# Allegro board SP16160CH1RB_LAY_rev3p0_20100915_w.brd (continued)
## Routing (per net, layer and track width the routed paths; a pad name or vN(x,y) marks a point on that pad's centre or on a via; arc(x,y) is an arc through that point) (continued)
ADC_CLK_N: length 20.5
  TOP w0.203: C173.1 98.73,90.91 98.73,97.69 95.5,100.91 95.5,105.33 C177.1 R162.1 95.5,107.01 95.5,109.17 95.58,109.24 U1.26
ADC_CLK_P: length 20.5
  TOP w0.203: C172.1 98.37,90.91 98.37,97.54 95.15,100.76 95.15,105.33 C174.1 R162.2 95.15,107.01 95.15,109.18 95.08,109.24 U1.25
ADC_VIN_IN: length 11.4
  TOP w0.203: 90.4,123.04 C73.2 90.07,122.7 v1(90.07,122.7) ; 90.4,123.04 90.4,123.04 90.78,123.04 92.15,121.67 92.15,121.08 91.69,120.62 L3.1 ; 90.4,123.04 90.4,123.42 89.39,124.43 88.85,124.43 88.08,123.66 88.08,123.23 L7.2 ; L3.1 91.69,120.52 92.15,120.07 92.15,119.2 92.08,119.13 92.08,118.83 U1.67 ; L3.1 v1(91.44,120.57)
  BOTTOM w0.203: C75.2 v1(90.07,122.7) ; R44.2 v1(91.44,120.57)
ADC_VIN_IP: length 12.3
  TOP w0.203: 92.96,120.57 92.96,120.52 92.51,120.07 92.51,119.2 92.58,119.13 92.58,118.83 U1.66 ; 92.96,120.57 92.96,120.62 92.51,121.08 92.51,121.82 91.03,123.29 91.03,123.67 91.04,123.67 ; 92.96,120.57 v1(93.22,120.57) ; 91.04,123.67 C73.1 91.37,124 v1(91.37,124) ; 91.04,123.67 90.65,123.67 89.53,124.79 88.71,124.79 87.83,123.91 87.4,123.91 L10.2
  BOTTOM w0.203: C74.1 v1(91.37,124) ; R43.1 v1(93.22,120.57)
ADC_VIN_QN: length 11
  TOP w0.203: 90.45,105.24 C83.2 90.3,105.38 v1(90.12,105.57) ; 90.45,105.24 90.45,105.23 90.81,105.23 92.15,106.58 92.15,107.16 91.69,107.62 L6.1 91.69,107.72 92.15,108.18 92.15,109.04 92.08,109.12 92.08,109.42 U1.19 ; 90.45,105.24 90.45,104.87 89.48,103.9 88.94,103.9 88.17,104.68 88.17,105.11 L8.2
  BOTTOM w0.203: v1(90.12,105.57) 90.43,105.25 C85.2 ; R49.2 v1(91.44,107.67)
ADC_VIN_QP: length 11.9
  TOP w0.203: 91.06,104.62 91.06,104.63 91.06,104.98 92.51,106.43 92.51,107.16 92.96,107.62 92.96,107.72 92.51,108.18 92.51,109.04 92.58,109.12 92.58,109.42 U1.20 ; 91.06,104.62 C83.1 91.21,104.48 v1(91.39,104.29) ; 91.06,104.62 90.7,104.62 89.62,103.54 88.8,103.54 87.92,104.42 87.49,104.42 87.38,104.32
  BOTTOM w0.203: 91.08,104.71 91.08,104.6 v1(91.39,104.29) ; R48.1 v1(93.22,107.67)
ADC_VRM_I: length 17.7
  TOP w0.203: C41.2 89.92,117.62 U1.2
  TOP w0.381: v1(89.61,120.93) C42.2 C41.2
  BOTTOM w0.508: R45.2 95,124.74 C43.1
  BOTTOM w0.635: C43.1 93.6,125.73 89.92,125.73 88.34,124.16 88.34,121.79 89.2,120.93 v1(89.61,120.93)
ADC_VRM_Q: length 17.3
  TOP w0.203: C44.2 89.71,109.93 89.71,110.06 90.28,110.62 U1.16
  TOP w0.381: C44.2 C45.2 v1(89.61,107.72)
  BOTTOM w0.508: C46.1 94.97,103.5 R50.2
  BOTTOM w0.635: C46.1 93.6,102.51 89.92,102.51 88.34,104.09 88.34,106.45 v1(89.61,107.72)
D0/1+I: length 35
  TOP w0.203: U1.60 95.5,118.9 95.5,127.41 98.88,130.78 119.34,130.78 H4.B5
D0/1+Q: length 29.3
  TOP w0.203: H4.B21 119.32,98.81 111.38,98.81 106.2,103.99 100.41,103.99 96.74,107.66 96.74,108.98 96.58,109.13 U1.28
D0/1-I: length 37.7
  TOP w0.203: H4.A5 120.98,131.14 98.73,131.14 95.15,127.56 95.15,118.89 U1.61
D0/1-Q: length 30.8
  TOP w0.203: U1.29 97.09,109.41 97.09,107.81 100.55,104.34 106.34,104.34 111.53,99.16 120.96,99.16 H4.A21
D2/3+I: length 32.4
  TOP w0.203: H4.B6 119.32,128.8 99.34,128.8 96.47,125.93 96.47,118.93 U1.58
D2/3+Q: length 27.1
  TOP w0.203: U1.30 97.61,109.39 97.61,108.28 99.7,106.2 106.96,106.2 112.37,100.79 119.33,100.79 H4.B20
D2/3-I: length 35.1
  TOP w0.203: H4.A6 120.96,129.16 99.19,129.16 96.11,126.08 96.11,118.86 U1.59
D2/3-Q: length 28.6
  TOP w0.203: H4.A20 120.98,101.14 112.52,101.14 107.11,106.55 99.84,106.55 98.08,108.31 U1.31
D4/5+I: length 30
  TOP w0.203: H4.B7 120.15,125.98 119.33,126.8 99.09,126.8 97.56,125.27 97.56,118.84 U1.56
D4/5+Q: length 25.1
  TOP w0.203: H4.B19 119.33,102.79 112.42,102.79 107.39,107.82 99.47,107.82 98.6,108.69 98.6,109.44 U1.32
D4/5-I: length 32.8
  TOP w0.203: H4.A7 120.97,127.15 98.94,127.15 97.21,125.42 97.21,118.95 U1.57
D4/5-Q: length 26.6
  TOP w0.203: U1.33 99.08,108.71 99.61,108.18 107.54,108.18 112.57,103.15 120.97,103.15 H4.A19
D6/7+I: length 26.2
  TOP w0.203: U1.54 98.58,121.85 101.52,124.79 119.33,124.79 H4.B8
D6/7+Q: length 23.1
  TOP w0.203: H4.B18 119.32,104.8 112.88,104.8 108.31,109.37 101.42,109.37 101.04,109.75 99.91,109.75 U1.34
D6/7-I: length 28.9
  TOP w0.203: U1.55 98.08,121.85 101.38,125.15 120.98,125.15 H4.A8
D6/7-Q: length 24.4
  TOP w0.203: H4.A18 120.97,105.16 113.02,105.16 108.45,109.73 101.57,109.73 101.18,110.12 U1.35
D8/9+I: length 23.8
  TOP w0.203: U1.52 99.49,118.91 99.49,120.8 101.47,122.78 119.34,122.78 H4.B9
D8/9+Q: length 21.8
  TOP w0.203: H4.B17 119.31,106.81 113.28,106.81 109.55,110.54 100.84,110.54 100.76,110.62 U1.36
D8/9-I: length 26.6
  TOP w0.203: H4.A9 120.98,123.14 101.33,123.14 99.14,120.95 99.14,118.88 U1.53
D8/9-Q: length 24
  TOP w0.203: H4.A17 120.96,107.16 113.43,107.16 109.7,110.9 101.09,110.9 100.87,111.12 U1.37
D10/11+I: length 21.5
  TOP w0.203: H4.B10 119.32,120.8 104.57,120.8 101.39,117.62 U1.50
D10/11+Q: length 21.4
  TOP w0.203: H4.B16 119.33,108.79 113.11,108.79 110.27,111.62 U1.38
D10/11-I: length 23.6
  TOP w0.203: H4.A10 120.96,121.16 104.42,121.16 101.39,118.12 U1.51
D10/11-Q: length 23.6
  TOP w0.203: U1.39 100.57,112.12 100.71,111.98 110.42,111.98 113.25,109.14 120.98,109.14 H4.A16
D12/13+I: length 21.1
  TOP w0.203: H4.B11 119.33,118.8 104.24,118.8 102.34,116.89 100.84,116.89 100.57,116.62 U1.48
D12/13+Q: length 21
  TOP w0.203: H4.B15 119.33,110.79 113,110.79 111.18,112.62 U1.40
D12/13-I: length 23.2
  TOP w0.203: U1.49 100.51,117.12 100.63,117.25 102.19,117.25 104.09,119.15 120.97,119.15 H4.A11
D12/13-Q: length 23.2
  TOP w0.203: U1.41 100.57,113.12 100.71,112.98 111.32,112.98 113.15,111.15 120.97,111.15 H4.A15
D14/15+I: length 20.7
  TOP w0.203: U1.46 100.56,115.62 100.74,115.8 103.12,115.8 104.11,116.79 119.33,116.79 H4.B12
D14/15+Q: length 20.6
  TOP w0.203: U1.42 113,113.62 113.82,112.8 119.32,112.8 H4.B14
D14/15-I: length 22.8
  TOP w0.203: H4.A12 120.98,117.14 103.97,117.14 102.98,116.15 100.31,116.15 U1.47
D14/15-Q: length 22.8
  TOP w0.203: H4.A14 120.96,113.16 113.96,113.16 113.14,113.98 100.63,113.98 100.48,114.12 U1.43
DVGA_CLK: length 115.9
  TOP w0.203: U3.2 71.46,115.4 v1(66.98,115.4) ; R77.1 SWGI.4
  BOTTOM w0.203: R4.1 112.42,90.91 104.01,90.91 98.83,96.09 73.96,96.09 66.98,103.07 v1(66.98,115.4) 66.98,118.24 69.06,120.32 71.91,120.32 91.06,139.47 91.06,146.33 92.33,147.6 ; R67.2 92.33,147.6 ; 92.33,147.6 SWGI.4
DVGA_CSC: length 110.3
  TOP w0.203: R75.1 SWGI.8 ; U3.32 72.14,117.27 72.03,117.38 69.64,117.38 v1(69.42,117.15)
  BOTTOM w0.203: SWGI.8 97.41,147.6 ; 97.41,147.6 R65.2 ; 97.41,147.6 96.14,146.33 96.14,141.2 94.79,139.85 93.78,139.85 72.62,118.69 69.88,118.69 69.42,118.24 v1(69.42,117.15) 69.42,104.14 73.25,100.3 77.01,100.3 77.98,99.34 100.94,99.34 101.63,100.03 R7.1
DVGA_SDI: length 110.4
  TOP w0.203: R76.1 SWGI.6 ; v1(68.61,115.95) 68.66,115.9 71.46,115.9 U3.1
  BOTTOM w0.203: R5.1 102.95,95.96 100.38,98.53 77.62,98.53 76.66,99.49 72.9,99.49 68.61,103.78 v1(68.61,115.95) 68.61,118.59 69.52,119.51 72.26,119.51 93.6,140.84 93.6,146.33 94.87,147.6 ; 94.87,147.6 SWGI.6 ; 94.87,147.6 R66.2
DVGA_SDO: length 118.3
  TOP w0.203: R74.1 SWGI.10 ; v1(67.79,117.88) v1(70.23,117.88) 72.21,117.88 72.64,117.45 72.64,116.53 U3.31
  BOTTOM w0.203: 99.95,147.6 98.68,146.33 98.68,140.79 97.61,139.73 96.34,139.73 95.25,138.63 93.73,138.63 72.97,117.88 v1(70.23,117.88) ; 99.95,147.6 R64.2 ; 99.95,147.6 SWGI.10 ; v1(67.79,117.88) 67.79,103.43 72.54,98.68 76.3,98.68 77.27,97.71 99.77,97.71 103.48,94.01 R6.1
OUTCLK+: length 22.4
  TOP w0.203: H4.A13 120.98,115.14 100.3,115.14 U1.45
OUTCLK-: length 20.3
  TOP w0.203: U1.44 100.58,114.62 100.74,114.78 119.34,114.78 H4.B13
REGSEQ: length 259.7
  TOP w0.381: R221.2 C252.1 R220.1
  TOP w0.508: R220.1 58.98,76.73 57.89,77.83 48.59,77.83 36.2,65.43 36.2,59.51 32.51,55.83 32.51,29.84 30.05,27.38 30.05,8.97 32.08,6.93 72.44,6.93 ; 72.44,6.93 86.39,6.93 91.82,12.37 R208.1 101.22,10.79 115.85,10.79 118.57,13.51 118.57,73.66 119.25,74.35 R206.1 ; 72.44,6.93 72.47,6.96 R202.1
SCB: length 4.2
  TOP w0.203: R1.2 116.13,97.99 H4.D21
SCLK: length 3.5
  BOTTOM w0.203: R4.2 R3.2 116.12,91.95 H4.D24
SDI: length 3.5
  BOTTOM w0.203: H4.D22 116.14,95.96 R5.2 R2.2
SDO: length 2.6
  BOTTOM w0.203: R6.2 116.12,94.01 H4.D23
VA1P8: length 87.6
  TOP w0.203: v1(90.88,109.75) 91.01,109.75 90.88,109.88 U1.17 ; U1.1 90.69,118.12 v1(90.45,118.36)
  TOP w0.762: 65.43,72.67 v1(63.83,72.67) C271.1 v1(62.48,73.58) ; 65.43,72.67 Z5.3 v1(66.8,72.67) v1(67.69,72.67) C270.1 ; 65.43,72.67 v1(65.43,74.02)
  POWER_L4 w0.406: TP17.1 70.82,69.7 ; TP17.1 72.26,68.25 ; TP17.1 70.82,66.8 ; TP17.1 69.37,68.25
  POWER_L4 w0.508: 91.67,110.31 91.19,110.79 91.19,111.02 ; 91.67,110.31 93.98,110.31 ; 91.67,110.31 91.44,110.31 ; 91.44,110.31 v1(90.88,109.75) 90.88,110.31 ; 91.44,110.31 90.88,110.31 ; 93.98,110.31 94.34,110.31 94.34,109.96 93.98,110.31 ; 91.19,111.02 90.88,110.72 90.88,110.31 ; 91.19,111.02 91.19,117.63 v1(90.45,118.36)
  POWER_L4 w1.27: 94.34,109.96 96.47,109.96 97.16,109.27 97.16,107.24 96.11,106.2 96.11,104.39 94.31,102.59 92.81,102.59 92.1,101.88 88.87,101.88 78.44,91.44 78.44,85.5 67.69,74.75 v1(67.69,72.67)
  BOTTOM w0.381: v1(90.45,118.36) 90.55,118.26 C23.1 91.01,118.21 C24.1 ; C28.2 90.83,109.7 v1(90.88,109.75) 90.96,109.83 C27.2
VA3P0: length 101
  TOP w0.203: U1.4 90.29,116.62 90.22,116.69 v1(90.22,116.79) ; v1(93.57,119.41) 93.58,119.4 U1.64 ; v1(90.12,111.51) 90.24,111.62 U1.14 ; v1(93.58,108.84) U1.22
  TOP w0.508: R220.2 v1(57.38,73.69)
  TOP w0.762: C250.1 C251.1 v1(57.38,73.69) ; C250.1 v1(54.53,75.13) ; C250.1 Z4.3 49.12,73.69 v1(49.1,73.66)
  TOP w1.016: Z4.3 v1(51.21,75.16)
  POWER_L4 w0.406: 57.23,82.25 TP15.1 ; TP15.1 58.67,80.8 ; TP15.1 58.67,83.69 ; TP15.1 60.12,82.25
  POWER_L4 w0.508: v1(93.57,119.41) 93.09,119.89 89.64,119.89 89.15,119.41 ; 89.51,116.08 v1(90.22,116.79) 90.17,116.79 89.51,117.45 ; 89.46,109.42 89.89,108.99 91.16,108.99 91.62,109.45 93.01,109.45 93.57,108.89 93.57,108.85 v1(93.58,108.84)
  POWER_L4 w1.016: 57.28,73.58 57.28,75.77 82.42,100.92 82.42,105.41 85.01,108 88.54,108 89.46,108.92 89.46,110.85 v1(90.12,111.51) 89.05,112.57 89.05,115.29 89.51,115.75 89.51,117.45 89.15,117.81 89.15,119.41
  BOTTOM w0.381: v1(93.57,119.41) 93.57,118.47 C33.1 C34.1 ; v1(90.12,111.51) 90.93,111.51 C25.2 C26.2 ; v1(93.58,108.84) 93.6,108.86 C35.1 C36.1 ; C22.1 C21.1 90.42,116.59 v1(90.22,116.79)
VAMP: length 38.1
  TOP w0.203: v1(74.65,111.15) 74.65,111.71 U3.14 ; U3.27 74.65,116.53 v1(74.65,117.09)
  TOP w0.508: C204.1 v1(38.66,78.26) C203.1 v1(41.4,78.26) ; Z1.3 v1(54.69,27.3) ; Z1.3 v1(50.98,27.3) ; Z1.3 v1(52.83,28.68)
  TOP w0.635: C205.1 C206.1 TP11.1
  POWER_L4 w0.406: 56.79,28.78 TP11.1 ; TP11.1 59.69,28.78 ; TP11.1 58.24,30.23 ; TP11.1 58.24,27.33
  BOTTOM w0.508: v1(70.94,111.28) 71.42,111.28 R34.2 ; R87.1 v3(68.2,145.47) ; R81.1 v3(83.44,145.47) ; R67.1 v3(92.33,145.47) ; R84.1 v3(75.82,145.47) ; R31.2 v1(71.53,116.84) ; R63.1 v3(102.49,145.47) ; R66.1 v3(94.87,145.47) ; R82.1 v3(80.9,145.47) ; C63.1 v1(74.65,111.15) C64.1 ; R65.1 v3(97.41,145.47) ; R61.1 v3(107.57,145.47) ; C61.1 v1(74.65,117.09) C62.1 ; R88.1 v3(65.66,145.47) ; R62.1 v3(105.03,145.47) ; R85.1 v3(73.28,145.47) ; R83.1 v3(78.36,145.47) ; R64.1 v3(99.95,145.47) ; R86.1 v3(70.74,145.47) ; R68.1 v3(89.79,145.47)
  vias: v1(76.5,110.82)
VIO1P8: length 60.2
  TOP w0.203: U1.62 94.58,119.39 v1(94.46,119.51)
  TOP w0.635: 115.11,80.98 TP18.1 ; 115.11,80.98 115.11,78 C225.1 ; 115.11,80.98 Z6.3
  TOP w0.762: C226.1 C225.1
  POWER_L4 w0.508: v1(94.46,119.51) 94.79,119.51
  POWER_L4 w1.27: TP18.1 112.73,105.33 98.55,119.51 94.79,119.51
  BOTTOM w0.381: v1(94.46,119.51) 94.49,119.48 C31.1 C32.1
VPLL: length 68
  TOP w0.203: U4.30 96.24,70.31 v1(96.55,70.61) 96.35,70.81 U4.31 ; 91.95,66.04 91.95,65.58 C103.2 ; 91.95,66.04 U4.18 ; 91.95,66.04 92.18,66.27 v1(92.2,66.27) 92.45,66.52 U4.19 ; 87.3,72.19 87.17,72.31 87.05,72.31 C111.2 ; 87.3,72.19 v1(87.3,72.16) ; 87.3,72.19 87.33,72.16 87.68,72.16 C101.2 87.83,72.31 U4.3 ; C105.2 95.96,64.8 v1(95.78,64.97) 95.78,65.38 C115.2 95.73,66.4 94.97,67.16 U4.24 ; U4.8 v1(87.95,69.81) ; R113.2 67.72,39.75 R114.2 69.67,41.3 v1(69.75,41.38) ; U4.33 v1(96.55,71.81) ; U4.22 v1(93.95,66.27)
  TOP w0.381: R116.1 v1(98.7,67.94)
  TOP w0.508: C134.2 v1(97.92,72.29)
  TOP w0.635: 88.19,29.69 v2(87.05,29.69) v2(86.03,29.69) Z2.3 v2(83.74,29.69) ; 88.19,29.69 v2(88.19,30.66) ; 88.19,29.69 v2(89.33,29.69)
  TOP w0.762: 84.89,31.93 v2(84.15,31.93) ; 84.89,31.93 C217.1 ; 84.89,31.93 v2(84.89,32.74) ; TP12.1 v2(84.89,32.74) ; v2(84.89,32.74) 84.91,32.72 C217.1 ; Z2.3 v2(84.89,30.84) 84.89,31.88 C217.1
  POWER_L4 w0.406: 83.44,34.57 TP12.1 ; TP12.1 86.34,34.57 ; TP12.1 84.89,33.12 ; TP12.1 84.89,36.02
  BOTTOM w0.381: v1(96.55,71.81) 96.54,71.81 C107.2 C117.2 ; C116.2 C106.2 v1(96.55,70.61) ; 93.62,66.6 v1(93.95,66.27) ; 93.62,66.6 C104.2 ; 93.62,66.6 C114.2 ; 88.27,69.8 88.25,69.81 v1(87.95,69.81) ; 88.27,69.8 C112.2 ; 88.27,69.8 C102.2 ; C113.2 v1(92.2,66.27)
  BOTTOM w0.508: JP1.1 69.75,45.75 v1(69.75,41.38) 70.66,42.29 v1(77.24,42.29) v1(80.39,42.29) 81.08,42.29 84.96,38.4 84.96,34.65 TP12.1
  vias: v1(91.14,59.99) v1(91.95,60.81) v1(91.95,59.18)
VPLLIO: length 57
  TOP w0.203: v3(90.58,75.26) C130.2 90.45,75.49 90.45,75.08 C125.2 90.45,74.83 U4.46 ; U4.13 89.45,66.07 C121.2 89.43,65.84 89.43,65.68 v1(89.56,65.56) 89.43,65.43 89.43,65.25 C126.2 ; v3(95.96,76.33) C127.2 95.96,75.67 C122.2 94.95,74.66 U4.37 ; U4.43 v1(91.95,74.65) ; U4.40 v1(93.45,74.65)
  TOP w0.254: U6.5 95.58,90.3 95,90.3 94.71,90.58 94.71,91.08 94.89,91.26 U6.7 U6.8 95.61,93.07 C175.1 R172.1
  TOP w0.381: C126.2 v1(89.56,64.54)
  TOP w0.508: v1(96.55,93.19) 96.52,93.17 C175.1
  TOP w0.635: v2(77.17,29.69) Z3.3 78.08,29.92 C218.1 v1(73.36,29.92)
  TOP w0.762: Z3.3 v2(78.31,30.89) C219.1 ; C219.1 78.33,31.93 v2(79.04,31.93) ; C219.1 v2(78.31,32.74) TP13.1
  POWER_L4 w0.406: TP13.1 78.31,36.12 ; TP13.1 79.76,34.67 ; TP13.1 76.86,34.67 ; TP13.1 78.31,33.22
  POWER_L4 w1.016: v1(96.55,93.19) 99.59,93.19 100.51,92.28 100.51,81.66 95.96,77.11 v3(95.96,76.33)
  BOTTOM w0.381: 91.95,74.52 C124.2 ; 91.95,74.52 91.95,74.53 v1(91.95,74.65) ; 91.95,74.52 C129.2 ; C128.2 93.41,74.52 ; 93.41,74.52 93.45,74.56 v1(93.45,74.65) ; 93.41,74.52 C123.2
VREF: length 2.8
  TOP w0.203: U1.9 v1(90.22,114.12)
  BOTTOM w0.381: 90.96,114.12 90.96,113.46 C29.1 ; 90.96,114.12 C30.1 ; 90.96,114.12 v1(90.22,114.12)
VREFOSC: length 28.5
  TOP w0.508: v2(90.22,46.48) C146.2 R121.2
  TOP w0.635: v2(93.83,26.26) C235.1 ; C235.1 v2(97.03,26.26) 98.7,26.26 ; C235.1 v2(94.97,27.23) ; 98.7,28.27 v2(98.7,27.43) L12.2 98.7,26.26 ; 98.7,28.27 v2(98.7,29.41) TP19.1 ; 98.7,28.27 C236.1 v2(99.7,28.27) ; 98.7,26.26 v2(100.43,26.26) ; v2(90.22,46.48) 91.41,46.48 Y3.6
  POWER_L4 w0.406: 97.26,31.9 TP19.1 ; TP19.1 100.15,31.9 ; TP19.1 98.7,30.45 ; TP19.1 98.7,33.35
  vias: v2(95.94,26.29)
VRNI: length 8.3
  TOP w0.203: C1.2 90.48,116.12 U1.5 U1.6 90.82,115.68 C1.2 ; C1.2 89.74,115.68 89.52,115.9 C2.2
  TOP w0.381: C2.2 C7.1 C9.1 C5.1 86.46,116.08 v1(86.08,116.46)
  BOTTOM w0.381: C3.2 85.04,117.5 v1(86.08,116.46)
VRNQ: length 8.4
  TOP w0.203: C11.2 89.7,111.94 C12.2 ; C11.2 90.2,112.12 U1.13 U1.12 90.45,112.62 90.11,112.28 C11.2
  TOP w0.381: v1(86,111.25) 86.44,111.68 C19.1 C17.1 C15.1 89.03,111.68 89.28,111.94 C12.2
  BOTTOM w0.381: v1(86,111.25) C13.2
VRPI: length 7.7
  TOP w0.203: C1.1 89.45,115.05 C2.1 ; C1.1 90.47,114.62 U1.8 U1.7 90.81,115.05 C1.1
  TOP w0.381: C2.1 89.36,115.14 88.93,115.14 88.77,115.29 C4.1 C6.1 C8.1 86.21,115.29 v1(86.11,115.19)
  BOTTOM w0.381: C3.1 85.17,115.19 v1(86.11,115.19)
VRPQ: length 8.2
  TOP w0.203: C11.1 90.14,112.92 90.35,113.12 U1.11 U1.10 90.85,113.59 90.37,113.59 90.04,113.27 C11.1 ; C11.1 89.47,112.92 C12.1
  TOP w0.381: v1(86.13,112.47) C16.1 C18.1 C14.1 88.72,112.47 89.2,112.95 C12.1
  BOTTOM w0.381: C13.1 85.19,112.47 v1(86.13,112.47)
VVCXO: length 24.7
  TOP w0.508: C155.2 v3(103.71,65.84) 107.01,65.84 Y2.6
  TOP w0.635: C238.1 v1(105.41,28.27) ; C238.1 L13.2 ; C238.1 TP20.1 ; L13.2 104.76,26.38 v1(104.75,26.39) ; L13.2 v1(108.51,26.38) 109.69,26.38 C237.1 ; C237.1 v1(111.58,26.06) ; C237.1 v1(110.01,27.23)
  POWER_L4 w0.406: TP20.1 106.4,33.35 ; TP20.1 104.95,31.9 ; TP20.1 106.4,30.45 ; TP20.1 107.85,31.9
N16787386: length 32.2
  TOP w0.254: v2(98.07,136.22) 98.07,137.31 98.25,137.49 U2.1 ; v2(98.07,136.22) 98.07,135.2 98.32,134.95 U2.3 ; v2(98.07,136.22) U2.2
  TOP w0.381: U2.8 104.85,137.69 C39.1 v2(105.79,139.01)
  BOTTOM w0.508: v2(98.07,136.22) 102.44,136.22 105.23,139.01 v2(105.79,139.01) 109.14,139.01 114.17,133.99 116.14,133.99 H4.D3
N16788767: length 15.8
  TOP w0.203: H4.B3 119.14,132.97 114.25,132.97 113.54,133.68 U2.5
N16789698: length 13.5
  TOP w0.203: U2.6 117.17,134.95 H4.C3
N16910308: length 17.8
  TOP w0.254: U11.5 v1(78.49,20.96) 78.49,21.37 C214.1
  TOP w0.381: U11.5 81.15,20.04 C215.1
  TOP w0.762: Z2.1 84.86,24.84 80.85,24.84 ; 80.85,24.84 78.33,24.84 Z3.1 ; 80.85,24.84 80.85,20.35 C215.1
  BOTTOM w0.254: v1(78.49,20.96) 78.49,21.19 R204.2
N16910312: length 3.4
  TOP w0.203: R202.2 R201.2
  TOP w0.254: R202.2 74.07,20.04 76.09,20.04 U11.8
N16910365: length 118.7
  TOP w0.203: R201.1 73.74,15.01 75.87,12.88 77.32,12.88 v1(77.39,12.95)
  TOP w0.254: R205.1 122.85,74.36 U16.6 124.92,75.89 C222.1 ; v2(102.84,15.14) 102.84,15.13 U17.6 102.07,13.68 R207.1
  TOP w0.381: U11.4 78.49,12.98 C212.1 ; C222.1 v1(125.3,74.45) ; v1(122.83,70.64) C221.1 v1(122.83,73.25) R205.1
  TOP w0.508: v1(78.46,9.22) 78.49,9.25 C211.1 v1(78.49,11.71) C212.1 77.42,12.98 v1(77.39,12.95) ; R207.1 v1(102.95,13.64) C232.1
  TOP w0.635: v1(104.75,12.45) 104.8,12.5 C232.1 v1(106.58,13.64) C231.1
  TOP w0.762: L11.2 v1(46.46,22.38) ; v1(109.45,13.67) 109.42,13.64 C231.1
  TOP w1.27: Z1.1 52.78,22.53 49.66,22.53 48.21,23.98 v1(47.75,23.98) L11.2 46.46,27.99 44.55,29.9 ; 44.55,29.9 R231.1 ; 44.55,29.9 R211.1 v4(39.9,29.9) v4(36.63,29.9) v4(34.47,29.9)
  BOTTOM w1.27: 26.47,47.4 v3(25.27,46.2) 24,44.93 15.52,44.93 v3(14.38,43.79) 12.75,42.16 v3(12.75,35.36) 12.75,28.85 v3(13.77,27.84) v3(20.57,27.84) 24.99,27.84 26.49,29.34 R232.1 v3(30.3,29.9) v4(34.47,29.9) v4(36.63,29.9) v4(39.9,29.9)
N16910417: length 4.1
  TOP w0.254: U11.6 v1(77.69,21.01) 77.69,22.16 C214.2
  BOTTOM w0.203: v1(77.69,21.01) 77.69,21.66 R204.1
  BOTTOM w0.381: R203.1 R204.1
N16910454: length 1.5
  TOP w0.203: C213.1 76.09,16.23 U11.1
N16910619: length 13.9
  TOP w0.762: POWER.1 42.27,18.16 C201.1 C202.1 L11.1 40.28,23.98 D1.1
N16910872: length 8.8
  TOP w0.254: U16.1 122.85,80.66 C223.1
  TOP w0.635: C224.1 Z6.1 C223.1
N16914166: length 58.3
  TOP w0.203: U4.4 88.42,71.81 88.24,71.63 83.77,71.63 79.76,67.61 79.76,65.23 67.16,52.63 57.91,52.63 54.1,48.82 54.1,40.92 R102.1
  TOP w0.254: R102.1 C141.2 R101.1
N16914374: length 53.2
  TOP w0.203: U4.5 88.76,71.27 84.81,71.27 80.92,67.39 80.92,63.32 69.06,51.46 58.27,51.46 55.07,48.26 55.07,43.18 56.06,42.19 v1(56.26,42.19) R104.1
N16914480: length 48.9
  TOP w0.203: R106.1 C143.2 R105.1 56.26,47.98 58.78,50.5 70.08,50.5 82.85,63.27 82.85,67.92 85.75,70.82 88.79,70.82 U4.6
N16915833: length 57.8
  TOP w0.203: v1(91.95,59.99) 87.25,55.3 84.07,55.3 72.64,43.87 72.64,39.8 71.53,38.68 65.61,38.68 R111.1 C144.2 66.55,39.65 ; v1(99.14,68.58) 96.49,68.58 96.29,68.78 95.63,68.78 U4.27
  BOTTOM w0.203: v1(99.14,68.58) 99.16,68.58 99.34,68.4 99.34,65.48 98.2,64.34 93.32,64.34 92.94,63.96 92.94,60.99 v1(91.95,59.99)
N16916282: length 40.8
  TOP w0.203: U4.11 87.46,68.31 86.74,67.59 86.74,63.55 73.46,50.27 73.46,46.61 71.35,44.5 68.28,44.5 66.45,42.67 R114.1
  TOP w0.508: R114.1 R112.1 C145.2
N16917059: length 2.5
  TOP w0.203: C161.2 C162.2 C163.2 R148.2
N16917150: length 1.7
  TOP w0.203: R149.2 C163.1 C162.1
N16918738: length 3.4
  TOP w0.254: R125.2 C151.2 C153.2 C152.2 R127.1
N16918746: length 1.8
  TOP w0.254: C152.1 C153.1 R126.2
N16919303: length 2
  TOP w0.203: U4.32 95.62,71.32 R148.1
N16919573: length 7.8
  TOP w0.203: U4.23 94.45,64.86 97.1,62.2 98.83,62.2 v1(98.86,62.18)
N16925537: length 2.8
  TOP w0.203: v3(100.94,70.1) R134.1 99.8,69.93 C157.2
N16925643: length 2.8
  TOP w0.203: C158.2 99.82,69.22 R135.2 R133.1
  vias: v3(100.94,69.04)
N16932838: length 5.1
  TOP w0.203: Y2.5 106.43,69.01 102.26,69.01 R133.2
N16933075: length 5.1
  TOP w0.203: Y2.4 106.43,70.33 102.36,70.33 R131.1
N16933884: length 1.3
  TOP w0.203: U4.29 96.79,69.81 C157.1
N16934135: length 1.3
  TOP w0.203: U4.28 96.81,69.31 C158.1
N16936974: length 2.1
  TOP w0.203: R111.2 H3.1
N16941769: length 11.7
  TOP w0.254: JP1.2 69.16,47.7 60.83,47.7 H3.10
N16945927: length 15.5
  TOP w0.203: 92.84,62.41 92.84,53.09 93.52,52.4 R123.2 R163.2 ; 92.84,62.41 C148.1 ; 92.84,62.41 R124.1
N16961545: length 9.4
  TOP w0.508: R121.1 R122.2 ; R122.2 C147.2 ; R122.2 91.41,43.28 Y3.1
N16966744: length 1.7
  TOP w0.203: U4.21 93.45,65.7 C149.2
N16967372: length 1.6
  TOP w0.203: U4.20 92.95,65.67 C148.2
N17069889: length 12.2
  TOP w0.203: 91.44,85.23 91.44,85.52 92.53,86.61 92.53,87.66 93.17,88.29 98.17,88.29 98.37,88.49 98.37,89.28 C172.2
  TOP w0.254: 91.44,85.23 91.44,84.89 90.88,84.33 90.2,84.33 R159.2
N17069899: length 6.9
  TOP w0.203: 91.44,81.8 91.44,81.51 92.53,80.42 92.53,79.53 v1(92.25,79.25)
  TOP w0.343: R159.1 R157.1 90.03,81.8 91.44,81.8
  BOTTOM w0.203: R156.2 92.1,79.4 v1(92.25,79.25)
N17069913: length 12.2
  TOP w0.203: T4.3 93.98,85.52 92.89,86.61 92.89,87.5 93.32,87.93 98.32,87.93 98.73,88.34 98.73,89.28 C173.2
  TOP w0.254: R160.2 95.22,84.33 94.54,84.33 93.98,84.89 T4.3
N17069923: length 5.6
  TOP w0.203: T4.4 93.98,81.51 92.89,80.42 92.89,79.53 v1(93.17,79.25)
  TOP w0.343: R160.1 R158.2 95.39,81.8 T4.4
N17069969: length 4.2
  TOP w0.203: R153.2 92.89,77.7 92.89,74.24 92.94,74.19 92.94,73.98 U4.41
N17078917: length 4.2
  TOP w0.203: U4.42 92.46,73.97 92.46,74.17 92.53,74.24 92.53,77.7 R152.2
  TOP w0.254: R171.2 R152.2
N17080344: length 5.3
  TOP w0.203: v1(93.83,77.11) 93.95,76.99 U4.39
  BOTTOM w0.203: v1(93.83,77.11) 93.83,77.04 93.73,77.14 92.94,77.14 92.25,77.83 R154.2
N17080704: length 5.6
  TOP w0.203: v1(94.77,77.52) 94.77,76.5 94.43,76.16 94.43,73.99 U4.38
  BOTTOM w0.203: R155.2 94.41,77.98 94.77,77.62 v1(94.77,77.52)
N17085389: length 1.9
  TOP w0.203: 97.38,73.56 97.14,73.31 U4.36
N17126548: length 2.1
  TOP w0.254: R102.2 H3.2
N17128064: length 2.1
  TOP w0.254: R104.2 H3.4
N17128444: length 2.1
  TOP w0.254: R106.2 H3.6
N17145640: length 1.6
  TOP w0.203: U4.25 96.02,67.81 96.72,67.11 R115.2
N17146037: length 1.4
  TOP w0.203: U4.26 95.64,68.28 96.22,68.28 96.55,67.94 R116.2
N17171025: length 1.6
  TOP w0.203: U4.16 90.95,65.56 C133.2
N17184058: length 4.3
  TOP w0.203: U4.9 87.18,69.31 v1(86.54,69.95)
  BOTTOM w0.508: C131.1 86.26,70.23 v1(86.54,69.95)
N17184483: length 1.9
  TOP w0.203: U4.10 87,68.81 C132.2
N17196113: length 2
  TOP w0.254: H3.3 R112.2
N17380188: length 8.7
  TOP w0.343: U13.5 48.81,66.72 48.82,66.73
  TOP w0.508: R218.2 49.25,69.85 C248.1 49.35,68.86 Z4.1 C249.1 50.8,66.73 48.82,66.73
N17380190: length 51.3
  TOP w0.305: U13.4 v1(48.57,62.13) v1(48.57,61.09)
  TOP w0.343: 45.44,66.73 46.17,66.73 U13.8
  TOP w0.508: v1(48.57,61.09) 48.57,59.89 C246.1 C245.1 48.62,55.52 R217.2
  TOP w0.635: 43.54,59.84 C244.2 C246.1
  TOP w0.762: 45.44,66.73 44.37,66.73 43.54,65.89 43.54,59.84
  TOP w1.27: R211.2 41.83,36.63 TP14.1 39.93,43.13 43.54,46.74 L22.2 43.54,59.84
N17380250: length 4.4
  TOP w0.254: C248.2 47.78,68.91 R218.1 R219.1
  TOP w0.508: C248.2 47.77,68.61 U13.6
N17380270: length 1.7
  TOP w0.203: C247.1 46.17,61.19 U13.1
N17418092: length 15.3
  TOP w0.203: 102.72,19.48 102.11,18.87 102.11,17.67 U17.1 102.52,17.63 102.72,17.83 102.72,19.48 ; 102.72,19.48 C234.1
  TOP w0.762: C233.1 106.06,22.28 L13.1 ; C233.1 C234.1 ; C233.1 99.05,22.28 L12.1
N17540898: length 3.5
  TOP w0.635: v1(92.71,85.12) T4.2
  BOTTOM w0.381: v1(92.71,85.12) 95.07,85.12 R161.2 C171.2
N17556627: length 12.1
  TOP w0.203: TP5.1 87.22,59.36 87.22,67.31 87.72,67.81 U4.12
N17951100: length 6.5
  TOP w0.203: 79.4,115.6 80.02,115.6 83.12,118.7 83.41,118.7 C72.1 ; 79.4,115.6 78.89,115.6 R42.2 ; 79.4,115.6 C79.2
N17951224: length 1.1
  TOP w0.343: L2.1 85.06,120.35 84.43,119.72
N17951350: length 1.1
  TOP w0.343: L1.1 84.52,120.89 C71.2
N17951477: length 6.2
  TOP w0.203: C71.1 82.87,119.24 82.87,118.95 79.87,115.95 79.4,115.95 ; C79.1 79.4,115.95 ; 79.4,115.95 78.89,115.95 R41.2
N18225867: length 16
  TOP w0.203: v1(100.51,79.04) 102.21,77.34 R131.2
  BOTTOM w0.203: v1(100.51,79.04) 100.48,79.04 99.11,80.42 R156.1
N19850383: length 1.3
  TOP w0.254: U6.6 C176.2
N19858006: length 11
  TOP w0.254: R173.1 v3(87.53,93.75) U5.4 93.5,93.17 R172.2 93.8,92.86 93.8,91.49 93.57,91.26 U6.2
N19891198: length 6.5
  TOP w0.203: 79.4,112.65 78.89,112.65 R47.2 ; 79.4,112.65 80.2,112.65 83.21,109.63 83.5,109.63 C82.1 ; 79.4,112.65 C80.2
N19891210: length 1.1
  TOP w0.343: L5.1 85.15,107.98 C82.2
N19891220: length 1.1
  TOP w0.343: C81.2 84.61,107.44 L4.1
N19891226: length 6.2
  TOP w0.203: C80.1 79.4,112.29 ; 79.4,112.29 80.05,112.29 82.96,109.38 82.96,109.09 C81.1 ; 79.4,112.29 78.89,112.29 R46.2
N19915962: length 54.3
  TOP w0.203: v1(77.32,110.82) 77.32,110.97 76.57,111.72 U3.16 ; v1(79.73,123.34) 79.73,133.86 72.01,141.58 72.01,148.23 SWGQ.6 R96.1
  BOTTOM w0.203: R86.2 SWGQ.6 ; v1(79.73,123.34) 79.73,117.63 82.98,114.38 82.98,112.83 80.98,110.82 v1(77.32,110.82)
N19915964: length 53
  TOP w0.203: v1(63.73,112.42) 63.78,112.37 71.49,112.37 U3.8 ; R93.1 SWGQ.12
  BOTTOM w0.203: v1(63.73,112.42) 63.73,120.07 77.09,133.43 77.09,146.33 78.36,147.6 ; R83.2 78.36,147.6 ; 78.36,147.6 SWGQ.12
N19915966: length 54.6
  TOP w0.203: R94.1 SWGQ.10 ; v1(62.92,111.61) 63.12,111.81 72.05,111.81 U3.9
  BOTTOM w0.203: v1(62.92,111.61) 62.92,120.42 73.13,130.63 73.13,131.67 74.55,133.1 74.55,146.33 75.82,147.6 ; 75.82,147.6 R84.2 ; 75.82,147.6 SWGQ.10
N19916068: length 56.8
  TOP w0.203: R95.1 SWGQ.8 ; U3.10 72.64,111.72 72.64,111.05 72.31,110.72 62.18,110.72 v1(62.1,110.79)
  BOTTOM w0.203: v1(62.1,110.79) 62.1,120.78 72.01,130.68 72.01,146.33 73.28,147.6 ; 73.28,147.6 SWGQ.8 ; 73.28,147.6 R85.2
N19916070: length 51.4
  TOP w0.203: R91.1 SWGQ.16 ; U3.6 71.48,113.36 66.04,113.36 v1(65.35,114.05)
  BOTTOM w0.203: R81.2 83.44,147.6 ; 83.44,147.6 SWGQ.16 ; 83.44,147.6 82.17,146.33 82.17,136.17 65.35,119.35 v1(65.35,114.05)
N19916116: length 52.2
  TOP w0.203: R92.1 SWGQ.14 ; v1(64.54,113.23) 64.9,112.88 71.48,112.88 U3.7
  BOTTOM w0.203: 80.9,147.6 79.63,146.33 79.63,134.8 64.54,119.71 v1(64.54,113.23) ; 80.9,147.6 SWGQ.14 ; 80.9,147.6 R82.2
N19916160: length 51.5
  TOP w0.203: R98.1 SWGQ.2 66.93,148.23 66.93,141.58 77.29,131.22 v1(77.29,120.9) ; v1(81.36,113.66) 81.15,113.87 76.29,113.87 U3.20
  BOTTOM w0.203: v1(81.36,113.66) 77.29,117.74 v1(77.29,120.9) ; R88.2 SWGQ.2
N19916168: length 52
  TOP w0.203: v1(82.17,113.18) 81.11,113.18 80.94,113.36 76.3,113.36 U3.19 ; v1(78.51,122.12) 78.51,132.54 69.47,141.58 69.47,148.23 SWGQ.4 R97.1
  BOTTOM w0.203: v1(82.17,113.18) 82.17,114.02 78.51,117.68 v1(78.51,122.12) ; R87.2 SWGQ.4
N19927061: length 1.2
  TOP w0.203: U3.23 77.42,115.37 77.44,115.4 R42.1
N19930621: length 1.2
  TOP w0.203: R47.1 77.44,112.83 77.39,112.87 U3.18
N19931174: length 1.3
  TOP w0.203: R41.1 77.42,116.13 77.27,115.98 76.61,115.98 76.5,115.87 U3.24
N19978393: length 47.1
  TOP w0.203: v1(82.17,124.28) 75.64,117.75 U3.25 ; R73.1 SWGI.12
  BOTTOM w0.203: SWGI.12 R63.2 101.22,146.25 101.22,141.58 98.55,138.91 96.8,138.91 v1(82.17,124.28)
N19978493: length 56
  TOP w0.203: v1(82.98,115.54) 81.79,114.35 76.31,114.35 U3.21 ; R71.1 SWGI.16
  BOTTOM w0.203: v1(82.98,115.54) 82.98,122.76 97.51,137.29 102.03,137.29 106.3,141.55 106.3,146.25 R61.2 SWGI.16
N19978527: length 52.9
  TOP w0.203: R72.1 SWGI.14 ; U3.22 76.3,114.86 80.67,114.86 v1(82.17,116.36)
  BOTTOM w0.203: SWGI.14 R62.2 103.76,146.25 103.76,141.58 100.28,138.1 97.16,138.1 82.17,123.11 v1(82.17,116.36)
N19978547: length 51.8
  TOP w0.203: U3.3 71.48,114.86 v1(66.17,114.86) ; R78.1 SWGI.2
  BOTTOM w0.203: R68.2 89.79,147.6 ; 89.79,147.6 88.52,146.33 88.52,141.02 66.17,118.67 v1(66.17,114.86) ; 89.79,147.6 SWGI.2
N20035799: length 8.7
  TOP w0.508: R238.2 63.63,68.45 C268.1 63.86,67.56 65.53,67.56 ; Z5.1 65.53,67.56 ; 65.53,67.56 65.43,67.46 C269.1 65.43,65.3 U15.5
N20035801: length 55.1
  TOP w0.305: v1(62.79,59.72) v1(62.79,60.68) U15.4
  TOP w0.343: 59.11,65.3 U15.8 ; 57.96,57.81 57.96,56.82 L24.2
  TOP w0.381: 59.11,65.3 59.11,65.3
  TOP w0.508: 57.96,57.81 58.57,58.42 C264.2 C266.1 ; v1(62.79,59.72) 62.79,58.43 C266.1 ; C266.1 62.79,55.78 62.74,55.73 R237.2
  TOP w0.762: 59.11,65.3 57.71,63.91 L24.2
  TOP w1.27: L24.2 57.71,54.53 56.46,53.29 54.51,53.29 44.98,43.76 44.98,38.89 TP16.1 R231.2
N20035851: length 4.3
  TOP w0.254: R239.1 62.1,68.71 R238.1 62.18,67.51 C268.2
  TOP w0.508: U15.6 61.99,67.33 C268.2
N20035871: length 1.7
  TOP w0.254: U15.1 60.4,59.79 C267.1
N20095878: length 20
  TOP w0.203: R1.1 106.88,97.99 v1(102.11,102.77) ; v1(96.09,108.79) 96.09,109.41 U1.27
  BOTTOM w0.203: v1(96.09,108.79) v1(102.11,102.77)
N20110879: length 24.5
  TOP w0.203: v1(102.62,99.21) v1(99.06,102.77) ; U1.24 v1(94.58,108.79)
  BOTTOM w0.203: v1(94.58,108.79) 96.42,106.95 96.42,105.41 v1(99.06,102.77) ; v1(102.62,99.21) 104.98,96.85 R2.1
N20111750: length 36.5
  TOP w0.203: v1(92.18,96.9) 92.13,96.9 91.85,97.18 91.85,101.5 93.78,103.43 93.78,106.65 94.59,107.47 94.59,107.92 94.08,108.43 U1.23
  BOTTOM w0.203: v1(92.18,96.9) 99.19,96.9 103.99,92.1 112.42,92.1 R3.1
N20255780: length 1.9
  TOP w0.203: U3.30 73.14,118.17 C54.2
N20256222: length 1.9
  TOP w0.203: C53.2 73.64,118.19 U3.29
N20256983: length 1.9
  TOP w0.203: U3.11 73.14,110.07 C57.2
N20256985: length 1.9
  TOP w0.203: U3.12 73.64,110.05 C58.2
N20301482: length 5.3
  TOP w0.203: U3.4 v1(70.13,114.37)
  BOTTOM w0.203: R32.1 71.52,114.37 v1(70.13,114.37)
  BOTTOM w0.254: v1(70.13,114.37) 70.08,114.37 70.16,114.45 71.45,114.45 R32.1
  BOTTOM w0.508: R31.1 R32.1
N20301496: length 2.7
  TOP w0.203: v1(70.71,113.87) 70.71,113.84 70.74,113.87 U3.5
  BOTTOM w0.203: R33.1 71,113.59 v1(70.71,113.87)
  BOTTOM w0.508: R34.1 R33.1
N20322732: length 3.3
  TOP w0.343: R23.1 C52.2 T1.6
N20327745: length 1
  TOP w0.343: R22.1 C52.1
N20329493: length 18.2
  TOP w0.343: 55.04,131.29 SMA_AMP_I.1 R21.1 C51.1
N20339212: length 4.2
  TOP w0.203: T1.3 72.11,122.73 73.2,121.64 73.2,120.04 72.97,119.81 C54.1
N20339230: length 4.2
  TOP w0.203: T1.1 74.65,122.73 73.56,121.64 73.56,120.04 73.79,119.81 C53.1
N20345473: length 3.3
  TOP w0.343: R26.1 C56.2 T2.4
N20345514: length 4.2
  TOP w0.203: C58.1 73.79,108.43 73.56,108.2 73.56,106.6 74.65,105.51 T2.3
N20345516: length 4.2
  TOP w0.203: T2.1 72.11,105.51 73.2,106.6 73.2,108.2 72.97,108.43 C57.1
N20345544: length 1
  TOP w0.343: C56.1 R25.1
N20345548: length 18.2
  TOP w0.343: C55.1 R24.1 72.09,96.98 SAM_AMP_Q.1 55.04,96.98
N20345595: length 2.4
  TOP w0.343: T2.6 C55.2
N20471540: length 2.6
  BOTTOM w0.203: R7.2 116.1,100.03 H4.D20
N20575382: length 3
  BOTTOM w0.508: R44.1 R43.2 C76.1 C77.1 R45.1
N20577573: length 3
  BOTTOM w0.508: R49.1 R48.2 C86.1 C87.1 R50.1
N20588383: length 12.6
  BOTTOM w0.254: U12.5 24.05,55.27 23.88,55.45 20.61,55.45 D2.2
  BOTTOM w0.343: R212.2 26.49,49.96 R213.1 24.36,51.99 C241.2 U12.5
N20593441: length 8.6
  BOTTOM w0.343: C242.2 18.9,54.94 18.9,53 ; 18.9,53 18.9,52.1 L21.1 ; 18.9,53 19.41,53.51 D3.1 21.87,54.45 U12.6
N20594215: length 37.2
  TOP w0.508: v2(39.62,58.27) 39.7,58.34 L22.1
  BOTTOM w0.343: C243.2 16.59,48.97 L21.2
  BOTTOM w0.508: v2(39.62,58.27) v2(37.21,58.27) 37.13,58.34 v2(32.59,58.34) R215.1 27.48,58.45 26.37,59.56 17.04,59.56 16.59,59.11 L21.2
N20600657: length 4.9
  BOTTOM w0.343: C242.1 19.98,57.05 D2.1 20.28,56.74 22.81,56.74 U12.1
N20605120: length 2.7
  BOTTOM w0.343: R213.2 R214.2 26.48,54.45 U12.4
N20610525: length 3.1
  BOTTOM w0.343: U12.3 25,58.33 25.02,58.34 R216.1 R215.2
N20652482: length 57.3
  TOP w0.508: L24.1 v2(54.64,56.57) 53.67,56.57 53.16,56.06 v2(53.16,56.08)
  BOTTOM w0.343: C263.2 16.59,31.55 L23.2
  BOTTOM w0.508: L23.2 16.59,40.69 18.03,42.14 26.21,42.14 27.43,40.92 R235.1 38.2,40.92 v2(51.41,54.13) 53.16,55.88 v2(53.16,56.08)
N20652502: length 4.9
  BOTTOM w0.343: U14.1 20.58,39.02 D4.1 19.98,39.62 C262.1
N20652526: length 8.6
  BOTTOM w0.343: C262.2 18.72,37.69 18.72,35.73 ; 18.72,35.73 19.08,36.08 D5.1 21.87,37.02 U14.6 ; 18.72,35.73 L23.1
N20652532: length 3
  BOTTOM w0.343: R235.2 R236.1 25,40.8 U14.3
N20652558: length 12.6
  BOTTOM w0.254: D4.2 20.61,38.02 23.85,38.02 24.05,37.82 U14.5
  BOTTOM w0.343: R232.2 R233.1 24.28,34.49 C261.2 U14.5
N20652626: length 2.7
  BOTTOM w0.343: R233.2 R234.2 26.43,37.02 U14.4
N20699758: length 2.6
  TOP w0.254: U16.4 121.55,74.36 R205.2 R206.2
N20706015: length 2.6
  TOP w0.254: U17.4 100.77,13.65 R207.2 R208.2
N20974895: length 4.1
  TOP w0.203: R123.1 Y3.4
N21782541: length 12.2
  TOP w0.381: U5.10 v3(84.99,85.98) 84.99,82.04 89.05,77.98 R171.1
N21835550: length 10.2
  TOP w0.343: v1(90.35,79.12) R151.2
  BOTTOM w0.343: v1(90.35,79.12) SMA_CLK.1
N21864410: length 17.3
  TOP w0.203: R127.2 C154.2 105.64,57.56 Y2.1
N22064666: length 1.3
  TOP w0.203: R46.1 77.29,112.27 76.61,112.27 76.5,112.37 U3.17
N22090895: length 18.4
  TOP w0.203: R164.2 106.15,53.16 96.62,53.16 R163.1
  TOP w0.343: R164.2 108.13,51.13 SMA_REF.1
N22120084: length 20.1
  BOTTOM w0.203: R128.2 C159.2
  BOTTOM w0.254: R130.1 107.14,60.05 C160.2 C164.2 C159.2
N22120092: length 2.2
  BOTTOM w0.254: R129.2 103.15,57.68 C164.1 C160.1
N22142576: length 1.7
  BOTTOM w0.203: R138.2 C165.2
  BOTTOM w0.254: R130.2 C165.2
N22153853: length 2.2
  BOTTOM w0.254: D6.1 110.48,68.01 R140.1 110.41,67.94 C150.1
N22154582: length 2.2
  BOTTOM w0.254: C166.1 110.39,71.22 R139.2 110.48,71.13 D6.2
N22165309: length 9.6
  BOTTOM w0.254: 105.69,73.41 105.69,73.02 106.22,72.49 C166.2 ; 105.69,73.41 102.39,70.1 R136.1 ; 105.69,73.41 Y4.1
N22166052: length 9.9
  BOTTOM w0.254: Y4.2 105.69,65.56 ; 105.69,65.56 R137.1 ; 105.69,65.56 105.69,66.32 106.05,66.67 C150.2
N22186748: length 2.3
  BOTTOM w0.254: R138.1 D6.3
N22241799: length 1.6
  TOP w0.343: L8.1 C88.2 L5.2
N22241801: length 1.6
  TOP w0.343: L4.2 C88.1 L9.1
N22241811: length 1.6
  TOP w0.343: L2.2 C78.2 L7.1
N22241813: length 1.6
  TOP w0.343: L10.1 C78.1 L1.2
N22290747: length 2.4
  TOP w0.343: T1.4 C51.2
N22296932:
  vias: v1(73.38,123.62)
N22299452:
  vias: v1(73.38,104.62)

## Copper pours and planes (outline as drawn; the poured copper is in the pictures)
GND on TOP: 80.92,114.22 80.92,114.2 89.36,105.77 91.06,107.47 91.06,120.75 89.26,122.55
GND on BOTTOM: 8.51,3.84 8.51,86.39 54.86,86.39 54.86,153.7 127.89,153.7 127.89,3.84 ; 6 cut-outs
GND on GROUND_L2, GROUND_L3, GROUND_L5: 8.51,3.84 8.51,86.39 54.86,86.39 54.86,153.7 127.89,153.7 127.89,3.84
GND on POWER_L4: 8.51,68.3 8.51,86.39 54.86,86.41 54.86,153.7 127.89,153.7 127.89,3.84 8.51,3.84 8.51,26.42 34.54,26.42 34.54,68.3 ; 5 cut-outs
(no net) on TOP: 8.51,3.84 8.51,86.39 54.86,86.39 54.86,153.72 127.89,153.72 127.89,131.85 98.43,131.85 94.44,127.86 94.44,119.86 93.24,119.86 93.24,123.09 90.81,125.53 87.17,125.53 78.66,117.02 77.6,117.02 76.02,115.44 76.02,112.98 77.77,111.23 78.84,111.23 87.25,102.82 90.78,102.82 93.24,104.95 93.24,108.61 95.91,108.61 95.91,105.87 104.6,97.18 127.86,97.18 127.89,3.84 ; 11 cut-outs
VA1P8 on POWER_L4: 59.94,65.33 59.28,65.99 59.28,71.78 73.48,85.98 77.33,85.98 73.1,81.71 65.99,74.6 68.86,74.6 76.66,82.4 81.92,82.4 85.22,85.7 85.22,83.92 93.34,83.92 93.34,80.72 86.56,80.72 71.17,65.33
VA3P0 on POWER_L4: 58.52,75.46 73,90.43 73.41,86.46 56.92,69.98 47.78,69.98 47.78,74.32 59.21,85.75 62.53,85.75 67.95,91.16 70.94,91.16 56.31,76.66 56.31,75.46
VAMP on POWER_L4: 54.86,153.7 109.96,153.7 109.96,140.77 76.96,140.77 76.96,100.71 62.38,86.13 59.05,86.13 47.4,74.47 47.4,69.6 58.04,69.6 58.04,31.14 60.22,31.14 60.22,25.81 48.89,25.78 48.89,30.89 34.54,30.89 34.54,86.39 54.86,86.39
VPLL on POWER_L4: 82.02,35.51 82.02,21.56 83.34,20.24 89.28,20.24 90.88,21.84 90.88,36.65 86.59,40.94 86.59,45.95 88.98,48.34 88.98,56.87 90.22,58.12 99.47,58.12 102.41,61.06 102.41,74.19 100.84,75.77 98.32,75.77 97.46,74.9 97.46,74.73 96.88,74.14 96.29,74.14 96.01,74.42 95,74.42 94.72,74.14 88.32,74.14 87.78,74.68 86.18,74.68 85.22,73.71 85.22,68.22 86.41,67.03 89.79,67.03 90.75,66.07 90.75,64.85 88.87,62.97 85.98,62.97 76.45,53.44 76.45,41.07
VPLLIO on POWER_L4: 81.31,21.51 80.14,20.35 77.37,20.35 67.89,29.82 63.78,32.81 63.78,54.08 69.16,54.08 72.8,57.71 72.8,66.29 86.89,80.39 96.47,80.39 97.28,79.58 97.28,74.85 96.77,74.35 96.37,74.35 96.01,74.7 94.56,74.7 94.21,74.35 88.57,74.35 87.99,74.93 85.93,74.93 84.89,73.89 84.89,68.02 86.16,66.75 89.64,66.75 90.5,65.89 90.5,64.85 89.31,63.65 85.9,63.65 75.69,53.44 75.69,40.61 81.31,35
VREFOSC on POWER_L4: 101.75,22.15 100.43,20.83 92.63,20.83 91.39,22.07 91.39,37.24 87.15,41.48 87.15,45.47 89.7,48.02 89.7,56.1 90.83,57.23 97.33,57.23 99.14,55.42 99.14,46 101.75,43.38
VVCXO on POWER_L4: 103.38,42.88 103.38,22.15 104.67,20.85 111.61,20.85 115.57,24.82 115.57,67.56 113.28,69.85 103.48,69.85 103.07,69.44 103.07,60.78 99.77,57.48 99.77,46.48
N16910365 on POWER_L4: 8.51,3.84 8.55,67.64 33.99,67.64 33.99,30.51 48.51,30.51 48.51,19.99 81.76,19.99 85.9,15.85 107.7,15.85 116.18,24.33 116.18,80.72 116.48,81.03 119.33,81.03 119.33,93.12 116.87,95.58 116.87,96.55 118.97,98.65 126.77,98.65 127.89,97.54 127.89,3.84

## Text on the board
BOTTOM: NATIONAL SEMICONDUCTOR LAYER6 | 551600511-001 REV A
Package Geometry/Pastemask Bottom: NATIONAL SEMICONDUCTOR LAYER6 PASTE
Ref Des/Silkscreen Bottom: UL94V-0 | MADE IN US | NATIONAL SEMICONDUCTOR LAYER6 SILK | 980600511-
User.Comments: NATIONAL SEMICONDUCTOR LAYER1 MASK | NATIONAL SEMICONDUCTOR LAYER6 MASK | 2 | 3 | SP16160CH1RB | ADDED CAPS. | ADDED INFO FOR BRADLEY KENNEDY | B | 3800 AUTOMATION WAY SUITE 100 | FORT COLLINS, CO 80525 | NATIONAL SEMICONDUCTOR | 05/12/2009 | 01/28/2010 | 07/12/2010 | 1
TOP: NATIONAL SEMICONDUCTOR LAYER1
Package Geometry/Pastemask Top: NATIONAL SEMICONDUCTOR LAYER1 PASTE
Ref Des/Silkscreen Top: NATIONAL SEMICONDUCTOR LAYER1 SILK | +5V | GND | MADE IN US | COPYRIGHT 2010 | REV 3.0 | SP16160CH1RB
GROUND_L2: NATIONAL SEMICONDUCTOR LAYER2
GROUND_L3: NATIONAL SEMICONDUCTOR LAYER3
POWER_L4: NATIONAL SEMICONDUCTOR LAYER4
GROUND_L5: NATIONAL SEMICONDUCTOR LAYER5
DIMENSION: FIGURE | SIZE | 0.01 | 0.012 | 0.013 | 0.0276 | 0.036 | 0.037 | 0.045 | 0.05 | 0.056 | 0.066 | 0.098 | 0.06 | 0.083 | DRILL CHART: TOP to BOTTOM | ALL UNITS ARE IN INCHES | TOLERANCE | +0.003/-0.003 | +0.005/-0.005 | PLATED | NON-PLATED | QTY | 418 | 364 | 3 | 193 | 96 | 6 | 10 | 32 | 15 | 2 | 5 | 8 | 4
COMPVAL_TYPE_TOP: NATIONAL SEMICONDUCTOR FAB DRAWING | BOB HOLTZ         05/12/2009 | ERIC MASSE        01/28/2010 | BOB HOLTZ         07/12/2K10 | B.  DIFFERENTIAL IMPEDANCE OF .008 INCH TRACES WITH .006 INCH SPACING BETWEEN TRACES ON | VENDOR MAY MODIFY TRACE WIDTH AND DIELECTRIC HEIGHTS BY 20% WITHOUT WRITTEN APPROVAL. | 10.  BOARD MUST HAVE RoHS CERTIFICATE. | 11.  PROVIDE LEAD FREE SYMBOL ON PCB. | LAYERS 1 AND 6 SHALL BE 100 OHMS +/- 10%
